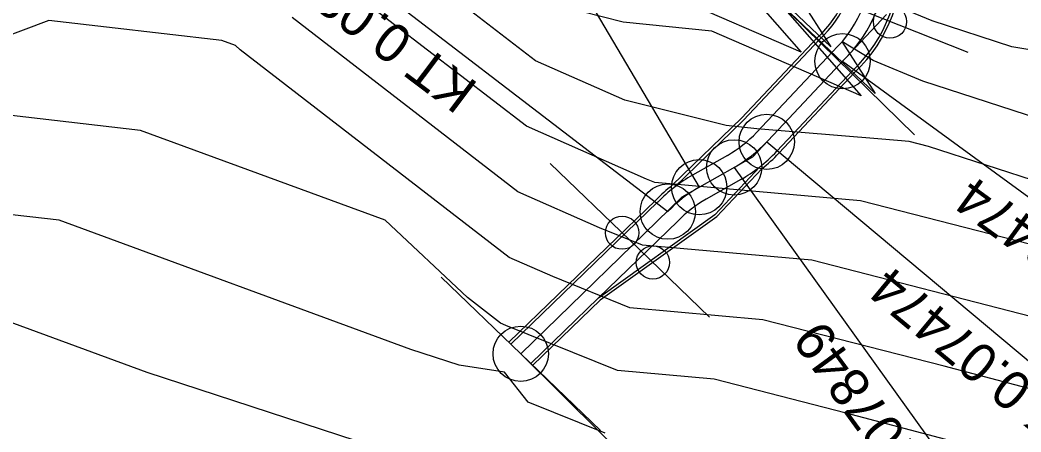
# Model space of a CAD drawing. Extents: x -549394 to -546608, y -1037055 to -1033629.
# Drawn here: x -547906.5 to -547816, y -1035644.5 to -1035607.2 of the extents above; entities that cross this region are included whole.
import ezdxf

# ---------------------------------------------------------------- set-up
doc = ezdxf.new("R2010")
doc.units = 0
for name, color, linetype in [('hlavni_vrst', 7, 'Continuous'), ('hrana_L', 7, 'Continuous'), ('norm_vrst', 7, 'Continuous'), ('POLYGONY_SITUACE_PO', 7, 'Continuous'), ('u_sirka_6m', 7, 'Continuous'), ('x_navrh_C111', 7, 'Continuous'), ('x_osa_C111', 7, 'Continuous'), ('x_popis_oblouky_C111', 7, 'Continuous'), ('x_popis_pricne_rezy_C111', 7, 'Continuous')]:
    doc.layers.add(name, color=color, linetype=linetype)

msp = doc.modelspace()

# ---------------------------------------------------------------- linework, layer by layer
at = {"layer": 'hlavni_vrst'}
for p, q in [((-547860.696, -1035616.846), (-547875.613, -1035605.342)), ((-547849.858, -1035621.627), (-547860.696, -1035616.846)), ((-547849.11, -1035621.929), (-547849.858, -1035621.627)), ((-547830.527, -1035623.581), (-547849.11, -1035621.929)), ((-547812.931, -1035628.102), (-547830.527, -1035623.581)), ((-547895, -1035639.079), (-547910.329, -1035633.456)), ((-547876.12, -1035645.254), (-547895, -1035639.079))]:
    msp.add_line(p, q, dxfattribs=at)
at = {"layer": 'hrana_L'}
msp.add_line((-547890.99, -1035553.63), (-547825.64, -1035617.62), dxfattribs=at)
at = {"layer": 'norm_vrst'}
for p, q in [((-547851.919, -1035591.888), (-547835.876, -1035610.134)), ((-547833.2, -1035609.662), (-547851.919, -1035591.888)), ((-547839.557, -1035599.689), (-547833.2, -1035609.662)), ((-547835.876, -1035610.134), (-547858.665, -1035600.275)), ((-547824.037, -1035607.327), (-547833.553, -1035603.361)), ((-547859.908, -1035610.921), (-547869.32, -1035603.662)), ((-547838.015, -1035605.503), (-547830.46, -1035614.095)), ((-547829.2, -1035613.873), (-547838.015, -1035605.503)), ((-547861.484, -1035622.771), (-547881.905, -1035607.021)), ((-547851.957, -1035607.426), (-547855.766, -1035606.476)), ((-547903.905, -1035607.285), (-547915.758, -1035611.739)), ((-547888.261, -1035609.087), (-547903.905, -1035607.285)), ((-547843.952, -1035608.258), (-547851.957, -1035607.426)), ((-547816.833, -1035609.668), (-547824.037, -1035607.327)), ((-547830.46, -1035614.095), (-547843.952, -1035608.258)), ((-547887.008, -1035609.547), (-547888.261, -1035609.087)), ((-547886.587, -1035609.943), (-547887.008, -1035609.547)), ((-547829.366, -1035610.906), (-547832.193, -1035609.176)), ((-547832.193, -1035609.176), (-547829.2, -1035613.873)), ((-547806.463, -1035611.422), (-547816.833, -1035609.668)), ((-547862.272, -1035628.696), (-547886.587, -1035609.943)), ((-547851.831, -1035614.484), (-547859.908, -1035610.921)), ((-547824.885, -1035612.773), (-547829.366, -1035610.906)), ((-547814.391, -1035616.184), (-547824.885, -1035612.773)), ((-547842.656, -1035616.773), (-547851.831, -1035614.484)), ((-547895.617, -1035617.21), (-547907.28, -1035615.867)), ((-547839.881, -1035617.062), (-547842.656, -1035616.773)), ((-547828.573, -1035617.993), (-547839.881, -1035617.062)), ((-547873.48, -1035625.331), (-547895.617, -1035617.21)), ((-547826.124, -1035618.211), (-547828.573, -1035617.993)), ((-547824.381, -1035618.659), (-547826.124, -1035618.211)), ((-547811.949, -1035622.699), (-547824.381, -1035618.659)), ((-547854.097, -1035626.029), (-547861.484, -1035622.771)), ((-547902.973, -1035625.333), (-547910.656, -1035624.448)), ((-547871.162, -1035637.003), (-547902.973, -1035625.333)), ((-547866.046, -1035632.318), (-547873.48, -1035625.331)), ((-547850.235, -1035627.59), (-547854.097, -1035626.029)), ((-547834.93, -1035628.951), (-547850.235, -1035627.59)), ((-547858.337, -1035630.431), (-547862.272, -1035628.696)), ((-547814.078, -1035634.308), (-547834.93, -1035628.951)), ((-547851.36, -1035633.252), (-547858.337, -1035630.431)), ((-547863.06, -1035634.621), (-547866.046, -1035632.318)), ((-547839.332, -1035634.321), (-547851.36, -1035633.252)), ((-547822.946, -1035638.531), (-547839.332, -1035634.321)), ((-547862.576, -1035634.834), (-547863.06, -1035634.621)), ((-547852.486, -1035638.914), (-547862.576, -1035634.834)), ((-547866.805, -1035638.428), (-547871.162, -1035637.003)), ((-547862.713, -1035639.068), (-547866.805, -1035638.428)), ((-547810.702, -1035641.762), (-547822.946, -1035638.531)), ((-547860.559, -1035641.766), (-547862.713, -1035639.068)), ((-547843.735, -1035639.692), (-547852.486, -1035638.914)), ((-547831.813, -1035642.754), (-547843.735, -1035639.692)), ((-547853.611, -1035644.575), (-547860.559, -1035641.766)), ((-547812.012, -1035647.979), (-547831.813, -1035642.754))]:
    msp.add_line(p, q, dxfattribs=at)
at = {"layer": 'POLYGONY_SITUACE_PO'}
for centre in [(-547832.138, -1035610.963), (-547838.996, -1035618.249), (-547841.935, -1035620.558), (-547845.095, -1035622.348), (-547847.935, -1035624.552), (-547861.232, -1035637.402)]:
    msp.add_circle(centre, 2.5, dxfattribs=at)
at = {"layer": 'u_sirka_6m'}
for centre in [(-547827.853, -1035607.388), (-547852.069, -1035626.462), (-547849.282, -1035629.146)]:
    msp.add_circle(centre, 1.5, dxfattribs=at)
at = {"layer": 'x_navrh_C111'}
for p, q in [((-547841.26, -1035616.118), (-547834.403, -1035608.831)), ((-547841.078, -1035616.289), (-547834.221, -1035609.003)), ((-547839.906, -1035617.393), (-547833.049, -1035610.106)), ((-547838.085, -1035619.106), (-547831.228, -1035611.819)), ((-547837.903, -1035619.277), (-547831.046, -1035611.991)), ((-547847.53, -1035622.175), (-547841.235, -1035616.09)), ((-547847.361, -1035622.36), (-547841.078, -1035616.289)), ((-547842.552, -1035619.47), (-547845.711, -1035621.261)), ((-547843.685, -1035624.836), (-547839.607, -1035620.497)), ((-547843.528, -1035625.035), (-547839.437, -1035620.682)), ((-547841.319, -1035621.645), (-547844.478, -1035623.436)), ((-547862.312, -1035636.361), (-547849.016, -1035623.512)), ((-547862.132, -1035636.535), (-547848.836, -1035623.685)), ((-547843.685, -1035624.836), (-547854.216, -1035632.368)), ((-547843.518, -1035625.024), (-547854.05, -1035632.556)), ((-547854.221, -1035632.364), (-547847.035, -1035625.419)), ((-547860.332, -1035638.269), (-547854.221, -1035632.364)), ((-547860.151, -1035638.442), (-547854.05, -1035632.556))]:
    msp.add_line(p, q, dxfattribs=at)
for centre, radius, start, end in [((-547848.099, -1035609.683), 11.25, 299.54105, 316.73819), ((-547848.099, -1035609.683), 13.75, 307.76201, 316.73819), ((-547848.099, -1035609.683), 14, 308.21725, 316.73819), ((-547848.099, -1035609.683), 13.75, 299.54105, 307.76201), ((-547838.932, -1035633.223), 13.75, 119.54105, 127.80988), ((-547838.932, -1035633.223), 14, 127.89155, 136.0787), ((-547838.932, -1035633.223), 13.75, 127.80988, 136.0787), ((-547838.932, -1035633.223), 11.25, 119.54105, 136.0787)]:
    msp.add_arc(centre, radius, start, end, dxfattribs=at)
for centre, major_axis, ratio, start_param, end_param in [((-547842.326, -1035602.402), (15.239, 0), 0.901672, 5.528124, 6.394041), ((-547842.326, -1035602.402), (15.489, 0), 0.903259, 5.528124, 6.394041), ((-547842.327, -1035602.402), (10.881, 0), 0.862163, 5.528126, 6.396156), ((-547842.326, -1035602.402), (11.129, 0), 0.86536, 5.528126, 6.394041), ((-547842.326, -1035602.402), (12.739, 0), 0.882376, 5.528124, 6.394041)]:
    msp.add_ellipse(centre, major_axis=major_axis, ratio=ratio, start_param=start_param, end_param=end_param, dxfattribs=at)
at = {"layer": 'x_osa_C111'}
for p, q in [((-547840.291, -1035619.626), (-547828.179, -1035606.755)), ((-547840.291, -1035619.626), (-547846.675, -1035623.244)), ((-547861.232, -1035637.402), (-547846.675, -1035623.244))]:
    msp.add_line(p, q, dxfattribs=at)
for centre, start, end in [((-547848.099, -1035609.683), 299.54105, 316.73819), ((-547838.932, -1035633.223), 119.54105, 136.0787)]:
    msp.add_arc(centre, 12.5, start, end, dxfattribs=at)
msp.add_ellipse((-547842.326, -1035602.402), major_axis=(13.989, 0), ratio=0.892887, start_param=5.528124, end_param=6.394041, dxfattribs=at)
at = {"layer": 'x_popis_oblouky_C111'}
for points in [[(-547866.464, -1035586.169), (-547845.095, -1035622.348)], [(-547881.279, -1035598.964), (-547847.935, -1035624.552)], [(-547832.138, -1035610.963), (-547799.248, -1035634.967)], [(-547838.996, -1035618.249), (-547807.758, -1035644.359)], [(-547841.935, -1035620.558), (-547818.189, -1035653.631)], [(-547861.232, -1035637.402), (-547831.855, -1035666.535)]]:
    msp.add_lwpolyline(points, dxfattribs=at)
at = {"layer": 'x_popis_pricne_rezy_C111'}
for points in [[(-547820.776, -1035610.184), (-547830.077, -1035606.51), (-547839.377, -1035602.836)], [(-547844.154, -1035634.084), (-547851.357, -1035627.148), (-547858.56, -1035620.211)], [(-547854.029, -1035644.339), (-547861.232, -1035637.402), (-547868.435, -1035630.465)]]:
    msp.add_lwpolyline(points, dxfattribs=at)

# ---------------------------------------------------------------- texts
at = {"layer": 'x_popis_oblouky_C111'}
for s, rotation, p in [('KT 0.08573', 142.95281, (-547864.955, -1035613.063)), ('KT 0.06474', 144.03739, (-547800.646, -1035635.48)), ('TK 0.07474', 140.33027, (-547809.157, -1035644.804)), ('KT 0.07849', 126.12943, (-547819.677, -1035653.689))]:
    msp.add_text(s, height=3.5, rotation=rotation, dxfattribs=at).set_placement(p)

doc.saveas('drawing.dxf')
